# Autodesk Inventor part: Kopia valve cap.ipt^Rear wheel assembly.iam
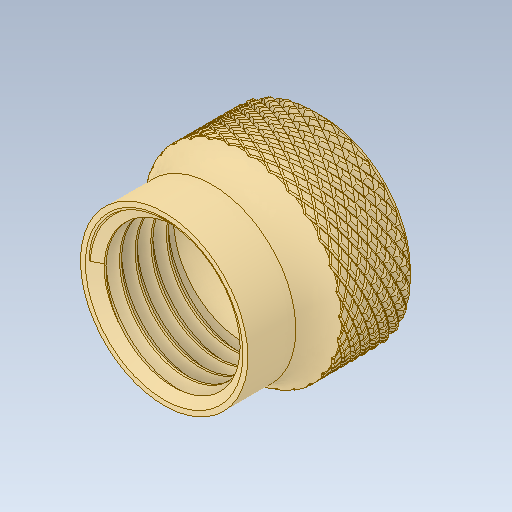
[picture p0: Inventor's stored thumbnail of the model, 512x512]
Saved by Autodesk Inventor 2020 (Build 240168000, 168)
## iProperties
Created: 2017-09
Part Number: Kopia valve cap.ipt^Rear wheel assembly.iam
Material: Ogólny
Document SubType Name: Modeling
Designer: Tomasz
Density: 1 g/cm^3
Appearance: Domyślna
Sending System: SolidWorks 2017
Last Author: Tomasz
Last Saved: 2017-09-11
Author: Tomasz
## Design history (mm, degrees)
feature "valve cap.ipt"
node "Bryła1"
